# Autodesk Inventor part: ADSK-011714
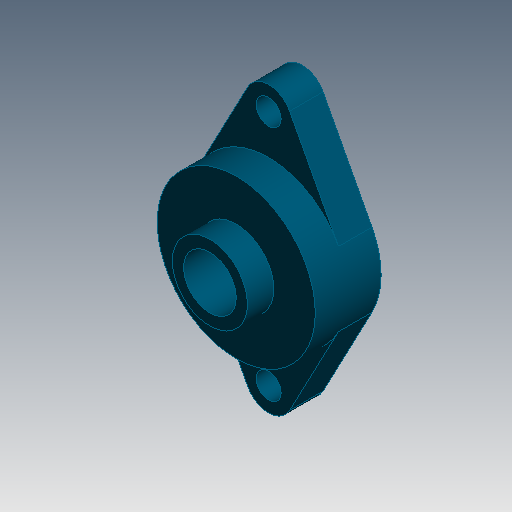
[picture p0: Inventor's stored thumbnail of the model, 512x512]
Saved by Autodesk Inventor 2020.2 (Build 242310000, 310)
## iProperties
Created: 1999-12
Part Number: ADSK-011714
Description: BEARING,FLG,0.750,2-BOLT
Document SubType Name: Modeling
Designer: KC
Material: Acier doux
Density: 7.86 g/cm^3
Appearance: Bearing Blue
Mass: 637.588 g
Surface Area: 168.253 cm^2
Volume: 81.118 cm^3
Control State: 0
Checked Out: False
Last Check In By: kcovelli
Master: False
Shininess: 20.0
Length Units: 11269
Angle Units: 11279
Time Units: 11290
Mass Units: 11283
Length Display Precision: 3
Angle Display Precision: 2
Compacted: True
Dimensions: 108x35x60 mm
Mass: 0,638 kg
DocNumber: ADSK-011714.ipt
Folder: 01 - Themengebiete\Simplification\01 - Packaging machine\
VDS_Category: 3D Komponenten
VLT_Material: Acier doux
Density: 7.859999999999999
Volumn: 86.01539176938044
Area: 174.50022473823603
PropertySet Name: Model Information
Author: KC
Revision Number: -
Title: bearing
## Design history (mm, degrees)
node "Extrusion1" dims "d8" = 12.7, "d9" = 0
  sketch "Sketch1"
    geometry: L1 (-26.533, -14)-(-7.96, -49.2); L2 (26.533, -14)-(7.96, -49.2); L3 (7.96, 49.2)-(26.533, 14); L4 (-7.96, 49.2)-(-26.533, 14); L5 (0, 45)-(0, -45); C1 r 4.75 at (0, 45); C2 r 4.75 at (0, -45); A1 r 30 centre (0, 0) between (-26.533, -14) and (26.533, -14); A2 r 9 centre (0, 45) between (7.96, 49.2) and (-7.96, 49.2); A3 r 9 centre (0, -45) between (-7.96, -49.2) and (7.96, -49.2); 1 further point
    constraints: 10 end point, 8 point on circle, 8 tangent, 5 centre point, 2 concentric, 2 equal radius, 2 point on line, 1 coincident, 1 midpoint, 1 parallel, 1 vertical
    dimensions: "d0" = 60 diameter of A1; "d5" = 9 radius of A2; "d6" = 9.5 diameter of C1; "d22" = 90 distance of A3.centre A2.centre
sketch "Sketch2"
  geometry: C1 r 30 at (0, 0); A1 r 30 centre (0, 0) between (26.533, -14) and (26.533, 14) reference; 3 further points
  constraints: 1 centre point, 1 coincident, 1 concentric, 1 other
node "Extrusion2" dims "d10" = 12.3, "d11" = 0
sketch "Sketch3"
  geometry: C1 r 14.25 at (0, 0)
  constraints: 1 centre point, 1 other
  dimensions: "d12" = 28.5 diameter of C1
node "Extrusion3" dims "d13" = 10, "d14" = 0
node "Hole1" dims "d15" = 20, "d16" = 9.525, "d17" = 6.35, "d18" = 60 deg, "d19" = 19.05, "d20" = 118 deg, "d24" = 6
workaxis "Work Axis1"
workaxis "Work Axis2"
workplane "Work Plane1"
node "Solide1"
node "Corps solides"
node "Corps surfaciques"
sketch "Sketch4"
  geometry: C1 r 14.25 at (0, 0) reference; 1 further point
